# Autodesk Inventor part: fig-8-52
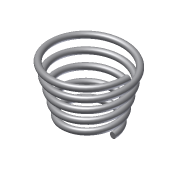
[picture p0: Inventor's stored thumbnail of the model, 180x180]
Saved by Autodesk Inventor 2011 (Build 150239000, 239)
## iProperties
Shininess: 77.0
Length Units: 11269
Angle Units: 11279
Time Units: 11290
Mass Units: 11283
Length Display Precision: 3
Angle Display Precision: 2
Created: 2002-01
Part Number: fig-8-52
Document SubType Name: Modeling
Designer: CADSoft
Density: 1 g/cm^3
Density: 0.0
Volumn: 0.0
Area: 0.0
PropertySet Name: Model Information
Control State: 0
Master: False
Checked Out: False
Author: CADSoft
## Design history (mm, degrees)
sketch "Sketch2"
  geometry: C1 r 2.5 at (-19.895, -0.092)
  constraints: 1 centre point
  dimensions: "d0" = 5 diameter of C1
coil "Coil5" sketch "Sketch2" pitch "d35" = 10; turns "d37" = 5; dims "d36" = 10, "d38" = 15 deg, angle "d39" = 90 deg, angle "d40" = 90 deg, "d41" = 0, "d42" = 0
body "Solid1"
